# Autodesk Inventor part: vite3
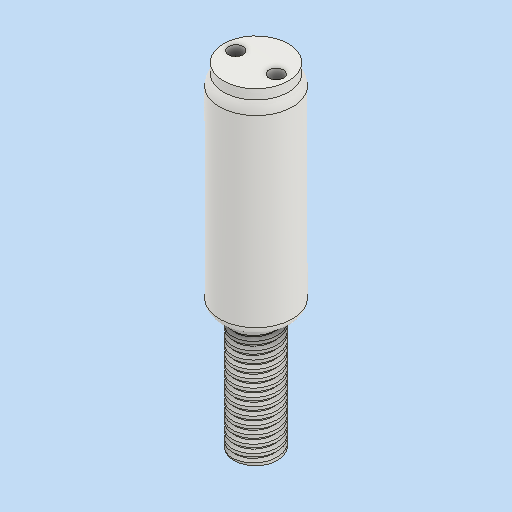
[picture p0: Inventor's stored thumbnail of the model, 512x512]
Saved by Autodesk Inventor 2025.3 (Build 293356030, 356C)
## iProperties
Created: 2026-05
Part Number: vite3
Material: Generico
Document SubType Name: Modeling
Designer: R5800u
Density: 1 g/cm^3
Appearance: Default
Mass: 1.77946 g
Surface Area: 14.9545 cm^2
Volume: 1.77946 cm^3
Sending System: Autodesk Translation Framework v15.8.0.0
Preprocessor: ST-DEVELOPER v20.1
Title: vite2.step
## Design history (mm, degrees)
node "Corpo1"
fillet "Raccordo1" dims "d0" = 0.5
sketch "Schizzo1"
  geometry: C1 r 4.5 at (1.928, 0.634) reference; A1 r 2.872 centre (1.928, 0.634) between (-0.747, 1.679) and (2.525, 3.443) reference; 4 further points
  constraints: 3 other
hole "Foro1" sketch "Schizzo1" at (1.928, 0.634) diameter "d1" = 2.5; stored, may be unused: countersink angle "d5" = 90 deg, drill point angle "d7" = 118 deg; dims "d2" = 6, "d3" = 4, "d4" = 2, "d6" = 20
sketch "Schizzo2"
  geometry: C1 r 2.75 at (1.928, 0.634); C2 r 3.343 at (1.928, 0.634); 1 further point
  constraints: 2 centre point, 2 coincident
  dimensions: "d8" = 5.5 diameter of C1
extrude "Estrusione1" cut sketch "Schizzo2" stored distance "d9" = 10; taper "d10" = 0 deg
sketch "Schizzo3"
  geometry: C1 r 1.25 at (0, 0) reference; C2 r 4 at (0, 0); C3 r 4.5 at (0, 0) reference; C4 r 0.9 at (-2.5, -0.003) reference; C5 r 0.9 at (2.5, 0) reference; 1 further point
  constraints: 1 centre point, 1 coincident
  dimensions: "d11" = 8 diameter of C2
extrude "Estrusione2" join sketch "Schizzo3" distance "d12" = 1.2; taper "d13" = 0 deg
fillet "Raccordo2" dims "d14" = 2
fillet "Raccordo3" dims "d15" = 1
node "Solido1"
node "Linea chiusa proiettata1"
node "Linea chiusa proiettata2"
